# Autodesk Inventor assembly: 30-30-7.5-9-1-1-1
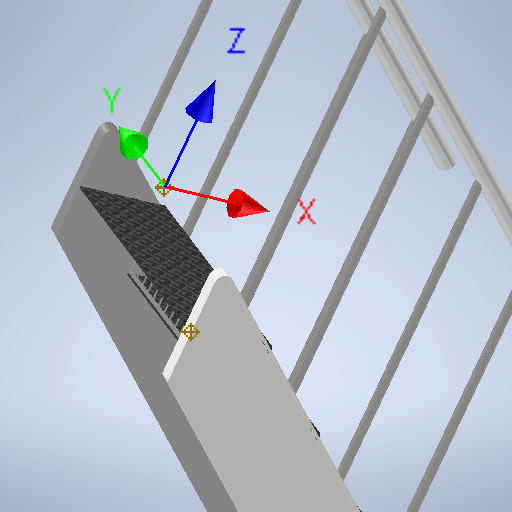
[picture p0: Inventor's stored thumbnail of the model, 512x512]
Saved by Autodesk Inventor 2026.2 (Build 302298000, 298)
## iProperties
RuleStatus: InUse
Company: Elevation Stair Company
Created: 2022-06
Part Number: 30-30-7.5-9-1-1-1
Document SubType Name: Assembly
Designer: David Reaume
Description: Metal Stairs
AfterAnyUserParamChange0: Type Name
Run: 9.000 in
TheAngle: 39.81 deg
TargetRise: 7.250 in
Rise: 7.500 in
Height: 30.000 in
Width: 30.000 in
StringerWidth: 10.000 in
StringerThickness: 1.500 in
StringerLength: 46.861 in
NumberOfSteps: 5.000 ul
Length: 36.000 in
TreadThickness: 1.250 in
StringerStockLength: 48.000 in
RailingStockLength: 46.861 in
RailingWidth: 3.000 in
RailingThickness: 2.000 in
RightRail: True
LeftRail: True
StringerMaterial: Steel, Galvanized
TreadMaterial: Steel, Wrought
RiserMaterial: Steel, Galvanized
BalusterMaterial: Steel, Galvanized
HandrailMaterial: Aluminum 6061
HasHandrail: True
HasRiser: True
BalusterLength: 36.000 in
BalusterDia: 1.000 in
INDDataset: sample
Author: David Reaume
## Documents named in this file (13)
- C:\Users\MichelleRasmussen\OneDrive\Documents\AutodeskTraining\Autodesk\Informed Design\Staircase Sample1\Staircase Sample\Staircase Sample.iam
- C:\Users\MichelleRasmussen\OneDrive\Documents\AutodeskTraining\Autodesk\Informed Design\Staircase Sample1\Staircase Sample\Stringer.ipt
- C:\Users\MichelleRasmussen\OneDrive\Documents\AutodeskTraining\Autodesk\Informed Design\Staircase Sample1\Staircase Sample\Tread.ipt
- C:\Users\MichelleRasmussen\OneDrive\Documents\AutodeskTraining\Autodesk\Informed Design\Staircase Sample1\Staircase Sample\Riser.ipt
- C:\Users\MichelleRasmussen\OneDrive\Documents\AutodeskTraining\Autodesk\Informed Design\Staircase Sample1\Staircase Sample\Baluster.ipt
- C:\Users\MichelleRasmussen\OneDrive\Documents\AutodeskTraining\Autodesk\Informed Design\Staircase Sample1\Staircase Sample\Railing.ipt
- C:\Users\MichelleRasmussen\OneDrive\Documents\AutodeskTraining\Autodesk\Informed Design\Staircase Sample1\Staircase Sample\Left Stringer_MIR.ipt
- D:\MID Staircase\Stringer.ipt
- D:\MID Staircase\Tread.ipt
- D:\MID Staircase\Riser.ipt
- D:\MID Staircase\Baluster.ipt
- D:\MID Staircase\Railing.ipt
- D:\MID Staircase\Left Stringer_MIR.ipt
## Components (20 placed, 7 different names)
1. Stringer
2. Left Stringer_MIR:1 — Mate:2
3. Right Railing
4. Left Railing — Flush:7, Flush:8, Flush:9
5. Tread:1 — Mate:1
6. Tread:2
7. Tread:3
8. Tread:4
9. Riser:1
10. Riser:2
11. Riser:3
12. Riser:4
13. Baluster:1
14. Baluster:12
15. Baluster:15
16. Baluster:17
17. Baluster:7 — Flush:11, Flush:12
18. Baluster:8
19. Baluster:13
20. Baluster:16
## Component patterns: Tread Pattern (4 elements), Riser Pattern (4 elements), Right Baluster Pattern (4 elements), Left Baluster Pattern (4 elements)
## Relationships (7: Flush 5, Mate 2)
- Flush:7: Left Railing
- Flush:8: Left Railing
- Flush:9: Left Railing
- Flush:11: Baluster:7
- Flush:12: Baluster:7
- Mate:1: Tread:1
- Mate:2: Left Stringer_MIR:1
## Named parameters: TheAngle = 6.94738 mm, StringerThickness = 38.1 mm, StringerLength = 1190.28205 mm, Length = 914.4 mm, TheAngleRounded = 6.94816 mm, StringerStockLength = 1219.2 mm, DiagonalTreadSpacing = 297.57051 mm, BalusterDia = 25.4 mm, BalusterLength = 914.4 mm, RailingStockLength = 1190.28205 mm, RailingWidth = 76.2 mm, RailingThickness = 50.8 mm, StringerSpacing = 876.3 mm
